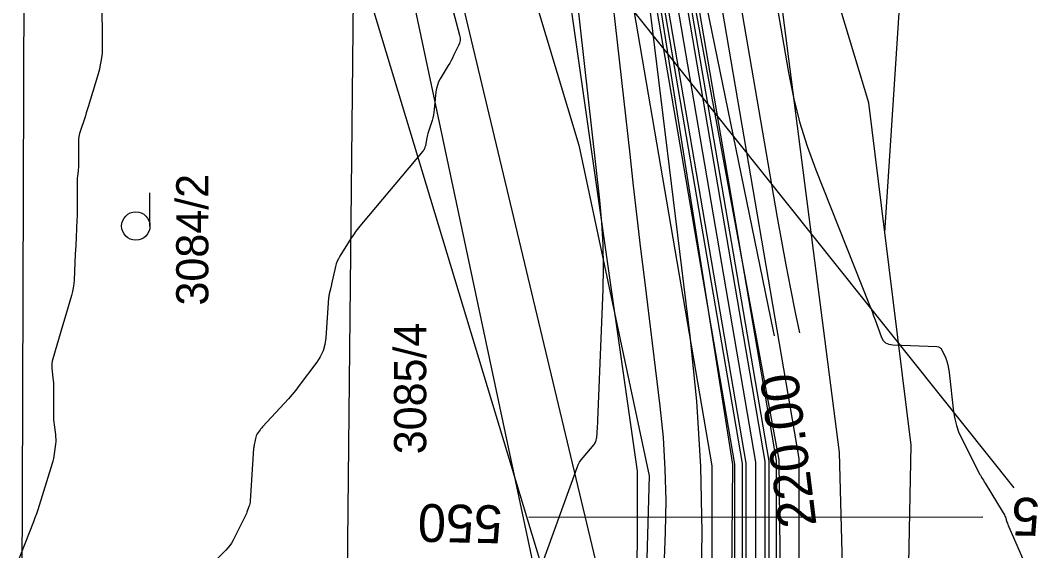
# Model space of a CAD drawing. Extents: x -534410 to -534262, y -1190162 to -1189584.
# Drawn here: x -534342.11 to -534315.26, y -1190023.79 to -1190009.78 of the extents above; entities that cross this region are included whole.
import ezdxf

# ---------------------------------------------------------------- set-up
doc = ezdxf.new("R2010")
doc.units = 0
for name, color, linetype in [('07_ELEKTRO', 7, 'Continuous'), ('30', 7, 'Continuous'), ('31', 7, 'Continuous'), ('40', 7, 'Continuous'), ('_linie', 7, 'Continuous'), ('_N_osa', 7, 'Continuous'), ('_N_tenká', 7, 'Continuous'), ('_N_tenká_velmi', 7, 'Continuous'), ('_N_text', 7, 'Continuous'), ('_přístup', 7, 'Continuous'), ('_tenka', 7, 'Continuous'), ('Default', 7, 'Continuous'), ('Hranice parcel', 7, 'Continuous'), ('Parcelní čísla', 7, 'Continuous'), ('Vrstva 12', 7, 'Continuous'), ('Značky kultur', 7, 'Continuous')]:
    doc.layers.add(name, color=color, linetype=linetype)

msp = doc.modelspace()

# ---------------------------------------------------------------- linework, layer by layer
at = {"layer": '07_ELEKTRO'}
msp.add_lwpolyline([(-534329.31, -1190087.46), (-534329.03, -1190079.95), (-534329.01, -1190078.66), (-534328.95, -1190069.47), (-534328.91, -1190061.75), (-534328.68, -1190054.09), (-534328.55, -1190046.44), (-534328.261, -1190025.497), (-534332.174, -1190007.081), (-534334.321, -1190004.167), (-534336.852, -1190002.737), (-534339.713, -1190001.803)], dxfattribs=at)
at = {"layer": '30'}
for points in [[(-534322.716, -1190005.85), (-534321.8, -1190011.157), (-534321.669, -1190011.814), (-534321.505, -1190012.462), (-534321.307, -1190013.1), (-534321.075, -1190013.729), (-534319.67, -1190017.258), (-534319.628, -1190017.366), (-534319.586, -1190017.474), (-534319.546, -1190017.583), (-534319.506, -1190017.692), (-534319.35, -1190018.129), (-534319.302, -1190018.225), (-534319.234, -1190018.295), (-534319.147, -1190018.338), (-534319.04, -1190018.356), (-534317.875, -1190018.4), (-534317.833, -1190018.406), (-534317.797, -1190018.422), (-534317.768, -1190018.449), (-534317.745, -1190018.484), (-534317.641, -1190018.702), (-534317.635, -1190018.716), (-534317.629, -1190018.73), (-534317.624, -1190018.744), (-534317.62, -1190018.758), (-534317.603, -1190018.816), (-534317.599, -1190018.83), (-534317.595, -1190018.845), (-534317.592, -1190018.859), (-534317.588, -1190018.874), (-534317.564, -1190018.987), (-534317.559, -1190019.011), (-534317.555, -1190019.035), (-534317.551, -1190019.058), (-534317.548, -1190019.083), (-534317.43, -1190020.126), (-534317.401, -1190020.306), (-534317.357, -1190020.481), (-534317.298, -1190020.651), (-534317.223, -1190020.817), (-534316.734, -1190021.776), (-534316.724, -1190021.795), (-534316.713, -1190021.815), (-534316.702, -1190021.834), (-534316.691, -1190021.854), (-534316.644, -1190021.93), (-534316.62, -1190021.968), (-534316.597, -1190022.006), (-534316.119, -1190022.787), (-534316.102, -1190022.816), (-534316.087, -1190022.846), (-534316.074, -1190022.877), (-534316.062, -1190022.908), (-534316.02, -1190023.036), (-534316.009, -1190023.068), (-534315.997, -1190023.1), (-534315.985, -1190023.131), (-534315.972, -1190023.162), (-534314.891, -1190025.641)], [(-534324.108, -1190025.034), (-534324.078, -1190023.301), (-534324.117, -1190021.569), (-534324.224, -1190019.841), (-534324.401, -1190018.116), (-534325.773, -1190006.894)], [(-534328.786, -1190025.46), (-534327.388, -1190021.594), (-534327.358, -1190021.522), (-534327.322, -1190021.453), (-534327.28, -1190021.388), (-534327.231, -1190021.326), (-534326.935, -1190020.982), (-534326.929, -1190020.975), (-534326.924, -1190020.968), (-534326.92, -1190020.96), (-534326.916, -1190020.952), (-534326.896, -1190020.912), (-534326.893, -1190020.905), (-534326.891, -1190020.897), (-534326.887, -1190020.878), (-534326.884, -1190020.867), (-534326.875, -1190020.835), (-534326.873, -1190020.829), (-534326.872, -1190020.822), (-534326.871, -1190020.815), (-534326.87, -1190020.809), (-534326.848, -1190020.537), (-534326.844, -1190020.49), (-534326.841, -1190020.442), (-534326.838, -1190020.395), (-534326.836, -1190020.347), (-534326.7, -1190016.893), (-534326.687, -1190016.302), (-534326.697, -1190015.711), (-534326.73, -1190015.122), (-534326.785, -1190014.533), (-534327.509, -1190008.078)], [(-534324.111, -1190008.706), (-534322.204, -1190017.993), (-534322.181, -1190018.116)], [(-534339.957, -1190009.113), (-534339.946, -1190010.519), (-534339.947, -1190010.581), (-534339.95, -1190010.643), (-534339.957, -1190010.704), (-534339.966, -1190010.765), (-534340.009, -1190011.01), (-534340.021, -1190011.071), (-534340.035, -1190011.132), (-534340.05, -1190011.192), (-534340.067, -1190011.251), (-534340.316, -1190012.066), (-534340.341, -1190012.145), (-534340.366, -1190012.223), (-534340.391, -1190012.301), (-534340.418, -1190012.379), (-534340.524, -1190012.689), (-534340.547, -1190012.767), (-534340.564, -1190012.847), (-534340.574, -1190012.927), (-534340.576, -1190013.009), (-534340.572, -1190013.596), (-534340.573, -1190013.635), (-534340.574, -1190013.673), (-534340.577, -1190013.711), (-534340.581, -1190013.75), (-534340.6, -1190013.902), (-534340.604, -1190013.941), (-534340.606, -1190013.979), (-534340.608, -1190014.017), (-534340.609, -1190014.056), (-534340.606, -1190014.628), (-534340.606, -1190014.736), (-534340.607, -1190014.844), (-534340.61, -1190014.953), (-534340.615, -1190015.061), (-534340.646, -1190015.726), (-534340.657, -1190015.955), (-534340.689, -1190016.634), (-534340.697, -1190016.739), (-534340.711, -1190016.842), (-534340.732, -1190016.945), (-534340.758, -1190017.046), (-534340.936, -1190017.651), (-534340.996, -1190017.853), (-534341.251, -1190018.722), (-534341.266, -1190018.783), (-534341.275, -1190018.846), (-534341.277, -1190018.908), (-534341.274, -1190018.972), (-534341.247, -1190019.226), (-534341.241, -1190019.29), (-534341.237, -1190019.354), (-534341.235, -1190019.418), (-534341.234, -1190019.482), (-534341.234, -1190020.207), (-534341.233, -1190020.271), (-534341.23, -1190020.335), (-534341.224, -1190020.399), (-534341.217, -1190020.463), (-534341.183, -1190020.717), (-534341.177, -1190020.781), (-534341.174, -1190020.845), (-534341.176, -1190020.908), (-534341.181, -1190020.972), (-534341.212, -1190021.232), (-534341.221, -1190021.296), (-534341.233, -1190021.359), (-534341.248, -1190021.422), (-534341.265, -1190021.485), (-534341.645, -1190022.709), (-534341.654, -1190022.736), (-534341.663, -1190022.763), (-534341.673, -1190022.79), (-534341.682, -1190022.817), (-534341.723, -1190022.922), (-534341.733, -1190022.949), (-534341.743, -1190022.975), (-534341.753, -1190023.002), (-534341.764, -1190023.028), (-534342.218, -1190024.189)]]:
    msp.add_lwpolyline(points, dxfattribs=at)
at = {"layer": '31'}
for points in [[(-534325.805, -1190043.543), (-534325.051, -1190023.305), (-534325.036, -1190022.469), (-534325.055, -1190021.635), (-534325.106, -1190020.801), (-534325.192, -1190019.969), (-534325.598, -1190016.645), (-534325.699, -1190015.814), (-534325.797, -1190014.982), (-534325.894, -1190014.15), (-534325.988, -1190013.318), (-534326.654, -1190007.39), (-534326.788, -1190006.444), (-534326.977, -1190005.511), (-534327.22, -1190004.59), (-534327.518, -1190003.682), (-534328.82, -1190000.077), (-534329.147, -1189999.176), (-534329.476, -1189998.275), (-534329.807, -1189997.376), (-534330.139, -1189996.477), (-534336.286, -1189979.943)], [(-534334.815, -1189980.466), (-534330.995, -1189988.966), (-534330.298, -1189990.512), (-534329.597, -1189992.056), (-534328.893, -1189993.598), (-534328.185, -1189995.139), (-534325.187, -1190001.643), (-534324.603, -1190003.024), (-534324.113, -1190004.435), (-534323.717, -1190005.875), (-534323.414, -1190007.344), (-534322.095, -1190014.986), (-534321.984, -1190015.614), (-534321.868, -1190016.242), (-534321.747, -1190016.868), (-534321.621, -1190017.494), (-534321.51, -1190018.033)], [(-534331.344, -1190006.955), (-534330.495, -1190010.169), (-534330.483, -1190010.24), (-534330.483, -1190010.31), (-534330.496, -1190010.378), (-534330.522, -1190010.445), (-534330.652, -1190010.711), (-534330.685, -1190010.778), (-534330.72, -1190010.843), (-534330.756, -1190010.907), (-534330.793, -1190010.971), (-534331.006, -1190011.325), (-534331.05, -1190011.406), (-534331.083, -1190011.491), (-534331.107, -1190011.579), (-534331.121, -1190011.671), (-534331.165, -1190012.133), (-534331.174, -1190012.206), (-534331.186, -1190012.279), (-534331.203, -1190012.35), (-534331.223, -1190012.421), (-534331.331, -1190012.765), (-534331.342, -1190012.805), (-534331.353, -1190012.845), (-534331.362, -1190012.886), (-534331.37, -1190012.927), (-534331.4, -1190013.091), (-534331.41, -1190013.131), (-534331.424, -1190013.168), (-534331.444, -1190013.204), (-534331.468, -1190013.237), (-534333.091, -1190015.166), (-534333.165, -1190015.257), (-534333.236, -1190015.35), (-534333.303, -1190015.446), (-534333.367, -1190015.544), (-534333.664, -1190016.013), (-534333.701, -1190016.077), (-534333.731, -1190016.143), (-534333.756, -1190016.212), (-534333.775, -1190016.283), (-534333.879, -1190016.748), (-534333.894, -1190016.812), (-534333.897, -1190016.828), (-534333.901, -1190016.844), (-534333.905, -1190016.86), (-534333.909, -1190016.877), (-534333.941, -1190017.003), (-534333.947, -1190017.029), (-534333.952, -1190017.056), (-534333.955, -1190017.082), (-534333.958, -1190017.11), (-534334.034, -1190018.171), (-534334.059, -1190018.345), (-534334.107, -1190018.51), (-534334.179, -1190018.666), (-534334.274, -1190018.814), (-534334.734, -1190019.429), (-534334.826, -1190019.55), (-534334.922, -1190019.667), (-534335.02, -1190019.782), (-534335.122, -1190019.894), (-534335.708, -1190020.522), (-534335.725, -1190020.541), (-534335.742, -1190020.56), (-534335.758, -1190020.58), (-534335.773, -1190020.601), (-534335.846, -1190020.699), (-534335.854, -1190020.711), (-534335.861, -1190020.725), (-534335.867, -1190020.739), (-534335.871, -1190020.754), (-534335.889, -1190020.829), (-534335.899, -1190020.875), (-534335.926, -1190020.99), (-534335.931, -1190021.014), (-534335.935, -1190021.039), (-534335.938, -1190021.064), (-534335.941, -1190021.088), (-534336.033, -1190022.471), (-534336.037, -1190022.51), (-534336.043, -1190022.549), (-534336.052, -1190022.586), (-534336.064, -1190022.623), (-534336.117, -1190022.771), (-534336.131, -1190022.807), (-534336.146, -1190022.844), (-534336.162, -1190022.879), (-534336.179, -1190022.914), (-534336.487, -1190023.517), (-534336.526, -1190023.588), (-534336.571, -1190023.655), (-534336.621, -1190023.718), (-534336.676, -1190023.777), (-534336.906, -1190024.008)]]:
    msp.add_lwpolyline(points, dxfattribs=at)
at = {"layer": '_linie'}
for points in [[(-534351.8, -1189951.99), (-534346.88, -1189964.25), (-534328.11, -1190005.55), (-534325.796, -1190021.686), (-534325.86, -1190050.97), (-534326.22, -1190078.56), (-534326.79, -1190120.4), (-534329.12, -1190134.93), (-534323.49, -1190133.89), (-534321.38, -1190121.46), (-534319.59, -1190053.22), (-534320.45, -1190021.195), (-534322.75, -1190003.33), (-534340.65, -1189960.04), (-534344.52, -1189948.89)], [(-534347.45, -1189950.137), (-534345.54, -1189954.54), (-534325.02, -1190005.35), (-534322.054, -1190021.393), (-534321.72, -1190051.56), (-534322.31, -1190078.15), (-534323.81, -1190120.37), (-534326.521, -1190134.45)], [(-534328.194, -1190134.759), (-534324.85, -1190120.45), (-534324.6, -1190078.17), (-534323.54, -1190051.92), (-534323.273, -1190021.516), (-534325.81, -1190005.43), (-534346.66, -1189954.59), (-534348.342, -1189950.518)]]:
    msp.add_lwpolyline(points, dxfattribs=at)
at = {"layer": '_N_osa'}
msp.add_lwpolyline([(-534327.357, -1190134.604), (-534324.33, -1190120.41), (-534323.455, -1190078.16), (-534322.63, -1190051.74), (-534322.663, -1190021.455), (-534325.415, -1190005.39), (-534346.1, -1189954.565), (-534347.892, -1189950.326)], dxfattribs=at)
at = {"layer": '_N_tenká'}
for points in [[(-534326.133, -1190134.378), (-534323.183, -1190120.543), (-534322.305, -1190078.19), (-534321.48, -1190051.757), (-534321.513, -1190021.356), (-534324.303, -1190005.072), (-534345.038, -1189954.124), (-534346.832, -1189949.878)], [(-534327.091, -1190134.555), (-534324.081, -1190120.439), (-534323.205, -1190078.166), (-534322.38, -1190051.744), (-534322.413, -1190021.433), (-534325.173, -1190005.321), (-534345.869, -1189954.469), (-534347.661, -1189950.228)], [(-534327.623, -1190134.654), (-534324.579, -1190120.381), (-534323.705, -1190078.154), (-534322.88, -1190051.736), (-534322.913, -1190021.476), (-534325.657, -1190005.459), (-534346.331, -1189954.661), (-534348.122, -1189950.423)], [(-534328.581, -1190134.83), (-534325.477, -1190120.277), (-534324.605, -1190078.13), (-534323.78, -1190051.723), (-534323.813, -1190021.553), (-534326.527, -1190005.708), (-534347.162, -1189955.006), (-534348.951, -1189950.773)]]:
    msp.add_lwpolyline(points, dxfattribs=at)
at = {"layer": '_N_tenká_velmi'}
for points in [[(-534326.772, -1190134.496), (-534323.781, -1190120.474), (-534322.905, -1190078.174), (-534322.08, -1190051.748), (-534322.113, -1190021.407), (-534324.883, -1190005.238), (-534345.592, -1189954.354), (-534347.385, -1189950.112)], [(-534326.985, -1190134.536), (-534323.981, -1190120.45), (-534323.105, -1190078.169), (-534322.28, -1190051.745), (-534322.313, -1190021.425), (-534325.076, -1190005.293), (-534345.777, -1189954.431), (-534347.569, -1189950.189)], [(-534327.943, -1190134.713), (-534324.879, -1190120.346), (-534324.005, -1190078.146), (-534323.18, -1190051.732), (-534323.213, -1190021.502), (-534325.947, -1190005.542), (-534346.608, -1189954.776), (-534348.398, -1189950.54)], [(-534327.73, -1190134.673), (-534324.679, -1190120.37), (-534323.805, -1190078.151), (-534322.98, -1190051.735), (-534323.013, -1190021.485), (-534325.754, -1190005.487), (-534346.423, -1189954.699), (-534348.214, -1189950.462)]]:
    msp.add_lwpolyline(points, dxfattribs=at)
at = {"layer": '_N_text'}
msp.add_lwpolyline([(-534316.661, -1190022.902), (-534328.661, -1190022.915)], dxfattribs=at)
at = {"layer": '_přístup'}
msp.add_lwpolyline([(-534330.552, -1190135.191), (-534328.648, -1190119.819), (-534326.845, -1190024.247), (-534332.805, -1189999.297), (-534354.454, -1189948.317)], dxfattribs=at)
at = {"layer": '_tenka'}
for points in [[(-534351.8, -1189951.99), (-534346.88, -1189964.25), (-534328.11, -1190005.55), (-534325.796, -1190021.686), (-534325.86, -1190050.97), (-534326.22, -1190078.56), (-534326.79, -1190120.4), (-534329.12, -1190134.93), (-534323.49, -1190133.89), (-534321.38, -1190121.46), (-534319.59, -1190053.22), (-534320.45, -1190021.195), (-534322.75, -1190003.33), (-534340.65, -1189960.04), (-534344.52, -1189948.89)], [(-534327.55, -1190134.64), (-534323.49, -1190133.89), (-534321.38, -1190121.46), (-534319.59, -1190053.22), (-534320.45, -1190021.195), (-534322.75, -1190003.33), (-534340.65, -1189960.04), (-534344.52, -1189948.89)], [(-534347.45, -1189950.137), (-534345.54, -1189954.54), (-534325.02, -1190005.35), (-534322.054, -1190021.393), (-534321.72, -1190051.56), (-534322.31, -1190078.15), (-534323.81, -1190120.37), (-534326.521, -1190134.45)], [(-534347.45, -1189950.137), (-534345.54, -1189954.54), (-534325.02, -1190005.35), (-534322.054, -1190021.393), (-534321.72, -1190051.56), (-534322.31, -1190078.15), (-534323.81, -1190120.37), (-534326.521, -1190134.45)], [(-534328.194, -1190134.759), (-534324.85, -1190120.45), (-534324.6, -1190078.17), (-534323.54, -1190051.92), (-534323.273, -1190021.516), (-534325.81, -1190005.43), (-534346.66, -1189954.59), (-534348.342, -1189950.518)], [(-534328.194, -1190134.759), (-534324.85, -1190120.45), (-534324.6, -1190078.17), (-534323.54, -1190051.92), (-534323.273, -1190021.516), (-534325.81, -1190005.43), (-534346.66, -1189954.59), (-534348.342, -1189950.518)], [(-534351.8, -1189951.99), (-534346.88, -1189964.25), (-534328.11, -1190005.55), (-534325.796, -1190021.686), (-534325.86, -1190050.97), (-534326.22, -1190078.56), (-534326.79, -1190120.4), (-534329.12, -1190134.93), (-534327.55, -1190134.64)]]:
    msp.add_lwpolyline(points, dxfattribs=at)
at = {"layer": 'Default'}
for points in [[(-534319.59, -1190053.22), (-534320.45, -1190021.195), (-534322.75, -1190003.33)], [(-534328.11, -1190005.55), (-534325.796, -1190021.686), (-534325.86, -1190050.97)]]:
    msp.add_lwpolyline(points, dxfattribs=at)
at = {"layer": 'Hranice parcel'}
for p, q in [((-534319.25, -1190015.38), (-534314.72, -1189945.99)), ((-534333.46, -1190024.63), (-534333.29, -1190007.81)), ((-534333.29, -1190007.81), (-534328.17, -1190024.72))]:
    msp.add_line(p, q, dxfattribs=at)
for points in [[(-534319.25, -1190015.38), (-534319.67, -1190011.96), (-534324.68, -1189995.39), (-534326.36, -1189991.44)], [(-534333.99, -1189993.03), (-534331.98, -1189997.67), (-534327.34, -1190013.08), (-534325.48, -1190021.81), (-534326.93, -1190073), (-534328.13, -1190128.3), (-534328.71, -1190131.86)], [(-534342.06, -1190024.47), (-534342.05, -1190022.37), (-534341.99, -1190003.45)], [(-534318.8, -1190033.53), (-534318.55, -1190021), (-534319.25, -1190015.38)]]:
    msp.add_lwpolyline(points, dxfattribs=at)
at = {"layer": 'Vrstva 12'}
msp.add_lwpolyline([(-534315.834, -1190022.126), (-534329.125, -1190005.478), (-534340.302, -1189991.272)], dxfattribs=at)
at = {"layer": 'Značky kultur'}
msp.add_line((-534338.682, -1190015.213), (-534338.682, -1190014.338), dxfattribs=at)
msp.add_circle((-534339.057, -1190015.213), 0.375, dxfattribs=at)

# ---------------------------------------------------------------- texts
at = {"layer": '40'}
msp.add_text('220.00', height=1, rotation=97.1056, dxfattribs=at).set_placement((-534321.054, -1190023.117))
at = {"layer": '_N_text'}
for s, rotation, p in [('550', 178.8361, (-534329.357, -1190022.598)), ('PF 5', 178.8836, (-534313.063, -1190022.442))]:
    msp.add_text(s, height=1, rotation=rotation, dxfattribs=at).set_placement(p)
at = {"layer": 'Parcelní čísla'}
for s, p in [('3084/2', (-534337.139, -1190017.313)), ('3085/4', (-534331.378, -1190021.243))]:
    msp.add_text(s, height=0.85, rotation=90, dxfattribs=at).set_placement(p)

doc.saveas('drawing.dxf')
